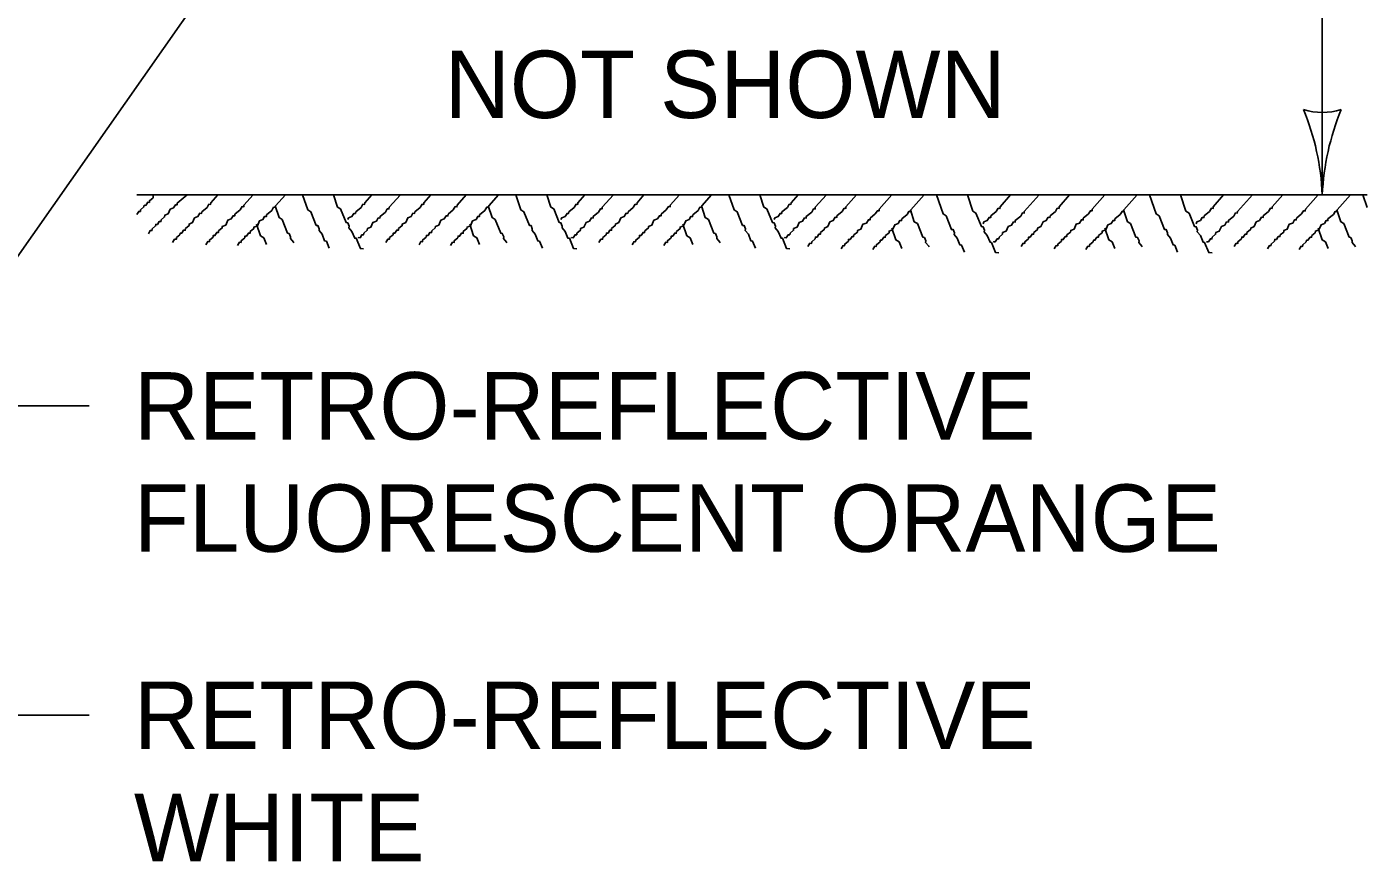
# Model space of a CAD drawing. Extents: x 49991.4 to 50024.6, y 49987.6 to 50011.4.
# Drawn here: x 50012.267 to 50013.46, y 49996.215 to 49996.958 of the extents above; entities that cross this region are included whole.
import ezdxf

# ---------------------------------------------------------------- set-up
doc = ezdxf.new("R2010")
doc.units = 0
for name, color, linetype in [('Level 1', 7, 'Continuous'), ('Level 2', 7, 'Continuous'), ('Level 3', 7, 'Continuous')]:
    doc.layers.add(name, color=color, linetype=linetype)

msp = doc.modelspace()

# ---------------------------------------------------------------- linework, layer by layer
at = {"layer": 'Level 1'}
for points in [[(50012.3796, 49996.8086), (50012.3794, 49996.806), (50012.3762, 49996.8033), (50012.3761, 49996.8018), (50012.3746, 49996.802), (50012.3729, 49996.7992), (50012.3715, 49996.7993), (50012.3713, 49996.7978), (50012.3682, 49996.7952), (50012.3681, 49996.7938), (50012.3666, 49996.7939), (50012.365, 49996.7912)], [(50012.4098, 49996.8086), (50012.4009, 49996.8012), (50012.4008, 49996.7997), (50012.3994, 49996.7998), (50012.3977, 49996.7971), (50012.3947, 49996.7958), (50012.3928, 49996.7917), (50012.3898, 49996.7904), (50012.3897, 49996.789), (50012.3865, 49996.7863), (50012.3864, 49996.7848), (50012.3849, 49996.7849), (50012.3832, 49996.7822), (50012.3818, 49996.7823), (50012.3816, 49996.7809), (50012.3785, 49996.7782), (50012.3784, 49996.7767), (50012.3769, 49996.7769), (50012.3752, 49996.774)], [(50012.4369, 49996.8086), (50012.4307, 49996.8016), (50012.4306, 49996.8001), (50012.4291, 49996.8002), (50012.4274, 49996.7974), (50012.4227, 49996.7934), (50012.4225, 49996.792), (50012.421, 49996.7922), (50012.4193, 49996.7894), (50012.4164, 49996.7881), (50012.4145, 49996.7839), (50012.4115, 49996.7826), (50012.4114, 49996.7812), (50012.4081, 49996.7786), (50012.408, 49996.7771), (50012.4066, 49996.7772), (50012.4049, 49996.7745), (50012.4035, 49996.7746), (50012.4033, 49996.7731), (50012.4002, 49996.7705), (50012.4001, 49996.769), (50012.3986, 49996.7691), (50012.3968, 49996.7663)], [(50012.4684, 49996.8086), (50012.4602, 49996.7994), (50012.4601, 49996.7979), (50012.4586, 49996.7981), (50012.4568, 49996.7953), (50012.4522, 49996.7913), (50012.4521, 49996.7899), (50012.4506, 49996.79), (50012.4489, 49996.7871), (50012.4458, 49996.786), (50012.444, 49996.7817), (50012.441, 49996.7805), (50012.4409, 49996.7791), (50012.4377, 49996.7765), (50012.4375, 49996.775), (50012.4361, 49996.7751), (50012.4344, 49996.7723), (50012.4329, 49996.7725), (50012.4328, 49996.771), (50012.4296, 49996.7683), (50012.4295, 49996.7668), (50012.4281, 49996.767), (50012.4264, 49996.7642)], [(50012.4971, 49996.8086), (50012.4884, 49996.7988), (50012.4882, 49996.7974), (50012.4867, 49996.7975), (50012.4851, 49996.7947), (50012.4803, 49996.7907), (50012.4802, 49996.7893), (50012.4787, 49996.7894), (50012.4771, 49996.7866), (50012.4741, 49996.7854), (50012.4722, 49996.7811), (50012.4691, 49996.7799), (50012.469, 49996.7785), (50012.4658, 49996.7759), (50012.4657, 49996.7744), (50012.4643, 49996.7745), (50012.4625, 49996.7717), (50012.4612, 49996.7718), (50012.461, 49996.7704), (50012.4578, 49996.7677), (50012.4577, 49996.7663), (50012.4563, 49996.7664), (50012.4545, 49996.7636)], [(50012.5125, 49996.8086), (50012.5171, 49996.7952), (50012.5198, 49996.7935), (50012.5246, 49996.7813), (50012.5261, 49996.7812), (50012.5272, 49996.7783), (50012.5271, 49996.7768), (50012.5298, 49996.7737), (50012.5321, 49996.7676), (50012.5336, 49996.7674), (50012.5362, 49996.7611)], [(50012.54, 49996.8086), (50012.5436, 49996.7977), (50012.5463, 49996.796), (50012.5512, 49996.7839), (50012.5527, 49996.7838), (50012.5539, 49996.7807), (50012.5537, 49996.7792), (50012.5564, 49996.7761), (50012.5589, 49996.77), (50012.5602, 49996.7699), (50012.5639, 49996.7608), (50012.5668, 49996.7606)], [(50012.574, 49996.8086), (50012.5678, 49996.8015), (50012.5677, 49996.8), (50012.5662, 49996.8002), (50012.5645, 49996.7974), (50012.5597, 49996.7934), (50012.5595, 49996.792), (50012.5581, 49996.7921), (50012.5564, 49996.7893), (50012.5534, 49996.7881), (50012.5527, 49996.7865)], [(50012.5995, 49996.8086), (50012.5894, 49996.7975), (50012.5893, 49996.796), (50012.5878, 49996.7961), (50012.5862, 49996.7933), (50012.5814, 49996.7894), (50012.5813, 49996.7879), (50012.5798, 49996.7881), (50012.5781, 49996.7853), (50012.5751, 49996.784), (50012.5732, 49996.7798), (50012.5701, 49996.7786), (50012.57, 49996.7771), (50012.5669, 49996.7744), (50012.5667, 49996.773), (50012.5653, 49996.7731), (50012.5636, 49996.7704), (50012.5622, 49996.7705), (50012.5622, 49996.7701)], [(50012.6266, 49996.8086), (50012.6204, 49996.8016), (50012.6203, 49996.8001), (50012.6188, 49996.8002), (50012.6171, 49996.7974), (50012.6124, 49996.7934), (50012.6122, 49996.792), (50012.6107, 49996.7922), (50012.609, 49996.7894), (50012.6061, 49996.7881), (50012.6042, 49996.7839), (50012.6012, 49996.7826), (50012.6011, 49996.7812), (50012.5978, 49996.7786), (50012.5977, 49996.7771), (50012.5963, 49996.7772), (50012.5946, 49996.7745), (50012.5932, 49996.7746), (50012.593, 49996.7731), (50012.5899, 49996.7705), (50012.5898, 49996.769), (50012.5883, 49996.7691), (50012.5865, 49996.7663)], [(50012.6581, 49996.8086), (50012.6499, 49996.7994), (50012.6498, 49996.7979), (50012.6483, 49996.7981), (50012.6465, 49996.7953), (50012.6419, 49996.7913), (50012.6418, 49996.7899), (50012.6403, 49996.79), (50012.6386, 49996.7871), (50012.6355, 49996.786), (50012.6337, 49996.7817), (50012.6307, 49996.7805), (50012.6306, 49996.7791), (50012.6274, 49996.7765), (50012.6272, 49996.775), (50012.6258, 49996.7751), (50012.6241, 49996.7723), (50012.6226, 49996.7725), (50012.6225, 49996.771), (50012.6193, 49996.7683), (50012.6192, 49996.7668), (50012.6178, 49996.767), (50012.6161, 49996.7642)], [(50012.6868, 49996.8086), (50012.6781, 49996.7988), (50012.6779, 49996.7974), (50012.6764, 49996.7975), (50012.6748, 49996.7947), (50012.67, 49996.7907), (50012.6699, 49996.7893), (50012.6684, 49996.7894), (50012.6668, 49996.7866), (50012.6638, 49996.7854), (50012.6619, 49996.7811), (50012.6588, 49996.7799), (50012.6587, 49996.7785), (50012.6555, 49996.7759), (50012.6554, 49996.7744), (50012.654, 49996.7745), (50012.6522, 49996.7717), (50012.6509, 49996.7718), (50012.6507, 49996.7704), (50012.6475, 49996.7677), (50012.6474, 49996.7663), (50012.646, 49996.7664), (50012.6442, 49996.7636)], [(50012.7022, 49996.8086), (50012.7068, 49996.7952), (50012.7095, 49996.7935), (50012.7143, 49996.7813), (50012.7158, 49996.7812), (50012.7169, 49996.7783), (50012.7168, 49996.7768), (50012.7195, 49996.7737), (50012.7218, 49996.7676), (50012.7233, 49996.7674), (50012.7259, 49996.7611)], [(50012.7297, 49996.8086), (50012.7333, 49996.7977), (50012.736, 49996.796), (50012.7409, 49996.7839), (50012.7424, 49996.7838), (50012.7436, 49996.7807), (50012.7434, 49996.7792), (50012.7461, 49996.7761), (50012.7486, 49996.77), (50012.7499, 49996.7699), (50012.7536, 49996.7608), (50012.7565, 49996.7606)], [(50012.7637, 49996.8086), (50012.7575, 49996.8015), (50012.7574, 49996.8), (50012.7559, 49996.8002), (50012.7542, 49996.7974), (50012.7494, 49996.7934), (50012.7492, 49996.792), (50012.7478, 49996.7921), (50012.7461, 49996.7893), (50012.7431, 49996.7881), (50012.7424, 49996.7865)], [(50012.7892, 49996.8086), (50012.7791, 49996.7975), (50012.779, 49996.796), (50012.7775, 49996.7961), (50012.7759, 49996.7933), (50012.7711, 49996.7894), (50012.771, 49996.7879), (50012.7695, 49996.7881), (50012.7678, 49996.7853), (50012.7648, 49996.784), (50012.7629, 49996.7798), (50012.7598, 49996.7786), (50012.7597, 49996.7771), (50012.7566, 49996.7744), (50012.7564, 49996.773), (50012.755, 49996.7731), (50012.7533, 49996.7704), (50012.7519, 49996.7705), (50012.7519, 49996.7701)], [(50012.8163, 49996.8086), (50012.8101, 49996.8016), (50012.81, 49996.8001), (50012.8085, 49996.8002), (50012.8068, 49996.7974), (50012.8021, 49996.7934), (50012.8019, 49996.792), (50012.8004, 49996.7922), (50012.7987, 49996.7894), (50012.7958, 49996.7881), (50012.7939, 49996.7839), (50012.7909, 49996.7826), (50012.7908, 49996.7812), (50012.7875, 49996.7786), (50012.7874, 49996.7771), (50012.786, 49996.7772), (50012.7843, 49996.7745), (50012.7829, 49996.7746), (50012.7827, 49996.7731), (50012.7796, 49996.7705), (50012.7795, 49996.769), (50012.778, 49996.7691), (50012.7762, 49996.7663)], [(50012.8478, 49996.8086), (50012.8396, 49996.7994), (50012.8395, 49996.7979), (50012.838, 49996.7981), (50012.8362, 49996.7953), (50012.8316, 49996.7913), (50012.8315, 49996.7899), (50012.83, 49996.79), (50012.8283, 49996.7871), (50012.8252, 49996.786), (50012.8234, 49996.7817), (50012.8204, 49996.7805), (50012.8203, 49996.7791), (50012.8171, 49996.7765), (50012.8169, 49996.775), (50012.8155, 49996.7751), (50012.8138, 49996.7723), (50012.8123, 49996.7725), (50012.8122, 49996.771), (50012.809, 49996.7683), (50012.8089, 49996.7668), (50012.8075, 49996.767), (50012.8058, 49996.7642)], [(50012.8765, 49996.8086), (50012.8678, 49996.7988), (50012.8676, 49996.7974), (50012.8661, 49996.7975), (50012.8645, 49996.7947), (50012.8597, 49996.7907), (50012.8596, 49996.7893), (50012.8581, 49996.7894), (50012.8565, 49996.7866), (50012.8535, 49996.7854), (50012.8516, 49996.7811), (50012.8485, 49996.7799), (50012.8484, 49996.7785), (50012.8452, 49996.7759), (50012.8451, 49996.7744), (50012.8437, 49996.7745), (50012.8419, 49996.7717), (50012.8406, 49996.7718), (50012.8404, 49996.7704), (50012.8372, 49996.7677), (50012.8371, 49996.7663), (50012.8357, 49996.7664), (50012.8339, 49996.7636)], [(50012.8919, 49996.8086), (50012.8965, 49996.7952), (50012.8992, 49996.7935), (50012.904, 49996.7813), (50012.9055, 49996.7812), (50012.9066, 49996.7783), (50012.9065, 49996.7768), (50012.9092, 49996.7737), (50012.9115, 49996.7676), (50012.913, 49996.7674), (50012.9156, 49996.7611)], [(50012.9194, 49996.8086), (50012.923, 49996.7977), (50012.9257, 49996.796), (50012.9306, 49996.7839), (50012.9321, 49996.7838), (50012.9333, 49996.7807), (50012.9331, 49996.7792), (50012.9358, 49996.7761), (50012.9383, 49996.77), (50012.9396, 49996.7699), (50012.9433, 49996.7608), (50012.9462, 49996.7606)], [(50012.9534, 49996.8086), (50012.9472, 49996.8015), (50012.9471, 49996.8), (50012.9456, 49996.8002), (50012.9439, 49996.7974), (50012.9391, 49996.7934), (50012.9389, 49996.792), (50012.9375, 49996.7921), (50012.9358, 49996.7893), (50012.9328, 49996.7881), (50012.9321, 49996.7865)], [(50012.9789, 49996.8086), (50012.9688, 49996.7975), (50012.9687, 49996.796), (50012.9672, 49996.7961), (50012.9656, 49996.7933), (50012.9608, 49996.7894), (50012.9607, 49996.7879), (50012.9592, 49996.7881), (50012.9575, 49996.7853), (50012.9545, 49996.784), (50012.9526, 49996.7798), (50012.9495, 49996.7786), (50012.9494, 49996.7771), (50012.9463, 49996.7744), (50012.9461, 49996.773), (50012.9447, 49996.7731), (50012.943, 49996.7704), (50012.9416, 49996.7705), (50012.9416, 49996.7701)], [(50013.0054, 49996.8086), (50012.9961, 49996.798), (50012.996, 49996.7965), (50012.9945, 49996.7966), (50012.9928, 49996.7938), (50012.9881, 49996.7898), (50012.9879, 49996.7884), (50012.9864, 49996.7886), (50012.9847, 49996.7858), (50012.9818, 49996.7845), (50012.9799, 49996.7803), (50012.9769, 49996.779), (50012.9768, 49996.7776), (50012.9735, 49996.775), (50012.9734, 49996.7735), (50012.972, 49996.7736), (50012.9703, 49996.7709), (50012.9689, 49996.771), (50012.9687, 49996.7695), (50012.9656, 49996.7669), (50012.9655, 49996.7654), (50012.964, 49996.7655), (50012.9622, 49996.7627)], [(50013.0369, 49996.8086), (50013.0256, 49996.7958), (50013.0255, 49996.7943), (50013.024, 49996.7945), (50013.0222, 49996.7917), (50013.0176, 49996.7877), (50013.0175, 49996.7863), (50013.016, 49996.7864), (50013.0143, 49996.7835), (50013.0112, 49996.7824), (50013.0094, 49996.7781), (50013.0064, 49996.7769), (50013.0063, 49996.7755), (50013.0031, 49996.7729), (50013.0029, 49996.7714), (50013.0015, 49996.7715), (50012.9998, 49996.7687), (50012.9983, 49996.7689), (50012.9982, 49996.7674), (50012.995, 49996.7647), (50012.9949, 49996.7632), (50012.9935, 49996.7634), (50012.9918, 49996.7606)], [(50013.0657, 49996.8086), (50013.0538, 49996.7952), (50013.0536, 49996.7938), (50013.0521, 49996.7939), (50013.0505, 49996.7911), (50013.0457, 49996.7871), (50013.0456, 49996.7857), (50013.0441, 49996.7858), (50013.0425, 49996.783), (50013.0395, 49996.7818), (50013.0376, 49996.7775), (50013.0345, 49996.7763), (50013.0344, 49996.7749), (50013.0312, 49996.7723), (50013.0311, 49996.7708), (50013.0297, 49996.7709), (50013.0279, 49996.7681), (50013.0266, 49996.7682), (50013.0264, 49996.7668), (50013.0232, 49996.7641), (50013.0231, 49996.7627), (50013.0217, 49996.7628), (50013.0199, 49996.76)], [(50013.0766, 49996.8086), (50013.0825, 49996.7916), (50013.0852, 49996.7899), (50013.09, 49996.7777), (50013.0915, 49996.7776), (50013.0926, 49996.7747), (50013.0925, 49996.7732), (50013.0952, 49996.7701), (50013.0975, 49996.764), (50013.099, 49996.7638), (50013.1016, 49996.7575)], [(50013.1042, 49996.8086), (50013.109, 49996.7941), (50013.1117, 49996.7924), (50013.1166, 49996.7803), (50013.1181, 49996.7802), (50013.1193, 49996.7771), (50013.1191, 49996.7756), (50013.1218, 49996.7725), (50013.1243, 49996.7664), (50013.1256, 49996.7663), (50013.1293, 49996.7572), (50013.1322, 49996.757)], [(50013.1425, 49996.8086), (50013.1332, 49996.7979), (50013.1331, 49996.7964), (50013.1316, 49996.7966), (50013.1299, 49996.7938), (50013.1251, 49996.7898), (50013.1249, 49996.7884), (50013.1235, 49996.7885), (50013.1218, 49996.7857), (50013.1188, 49996.7845), (50013.1181, 49996.7829)], [(50013.1681, 49996.8086), (50013.1548, 49996.7939), (50013.1547, 49996.7924), (50013.1532, 49996.7925), (50013.1516, 49996.7897), (50013.1468, 49996.7858), (50013.1467, 49996.7843), (50013.1452, 49996.7845), (50013.1435, 49996.7817), (50013.1405, 49996.7804), (50013.1386, 49996.7762), (50013.1355, 49996.775), (50013.1354, 49996.7735), (50013.1323, 49996.7708), (50013.1321, 49996.7694), (50013.1307, 49996.7695), (50013.129, 49996.7668), (50013.1276, 49996.7669), (50013.1276, 49996.7665)], [(50013.1951, 49996.8086), (50013.1858, 49996.798), (50013.1857, 49996.7965), (50013.1842, 49996.7966), (50013.1825, 49996.7938), (50013.1778, 49996.7898), (50013.1776, 49996.7884), (50013.1761, 49996.7886), (50013.1744, 49996.7858), (50013.1715, 49996.7845), (50013.1696, 49996.7803), (50013.1666, 49996.779), (50013.1665, 49996.7776), (50013.1632, 49996.775), (50013.1631, 49996.7735), (50013.1617, 49996.7736), (50013.16, 49996.7709), (50013.1586, 49996.771), (50013.1584, 49996.7695), (50013.1553, 49996.7669), (50013.1552, 49996.7654), (50013.1537, 49996.7655), (50013.1519, 49996.7627)], [(50013.2266, 49996.8086), (50013.2153, 49996.7958), (50013.2152, 49996.7943), (50013.2137, 49996.7945), (50013.2119, 49996.7917), (50013.2073, 49996.7877), (50013.2072, 49996.7863), (50013.2057, 49996.7864), (50013.204, 49996.7835), (50013.2009, 49996.7824), (50013.1991, 49996.7781), (50013.1961, 49996.7769), (50013.196, 49996.7755), (50013.1928, 49996.7729), (50013.1926, 49996.7714), (50013.1912, 49996.7715), (50013.1895, 49996.7687), (50013.188, 49996.7689), (50013.1879, 49996.7674), (50013.1847, 49996.7647), (50013.1846, 49996.7632), (50013.1832, 49996.7634), (50013.1815, 49996.7606)], [(50013.2554, 49996.8086), (50013.2435, 49996.7952), (50013.2433, 49996.7938), (50013.2418, 49996.7939), (50013.2402, 49996.7911), (50013.2354, 49996.7871), (50013.2353, 49996.7857), (50013.2338, 49996.7858), (50013.2322, 49996.783), (50013.2292, 49996.7818), (50013.2273, 49996.7775), (50013.2242, 49996.7763), (50013.2241, 49996.7749), (50013.2209, 49996.7723), (50013.2208, 49996.7708), (50013.2194, 49996.7709), (50013.2176, 49996.7681), (50013.2163, 49996.7682), (50013.2161, 49996.7668), (50013.2129, 49996.7641), (50013.2128, 49996.7627), (50013.2114, 49996.7628), (50013.2096, 49996.76)], [(50013.2663, 49996.8086), (50013.2722, 49996.7916), (50013.2749, 49996.7899), (50013.2797, 49996.7777), (50013.2812, 49996.7776), (50013.2823, 49996.7747), (50013.2822, 49996.7732), (50013.2849, 49996.7701), (50013.2872, 49996.764), (50013.2887, 49996.7638), (50013.2913, 49996.7575)], [(50013.2939, 49996.8086), (50013.2987, 49996.7941), (50013.3014, 49996.7924), (50013.3063, 49996.7803), (50013.3078, 49996.7802), (50013.309, 49996.7771), (50013.3088, 49996.7756), (50013.3115, 49996.7725), (50013.314, 49996.7664), (50013.3153, 49996.7663), (50013.319, 49996.7572), (50013.3219, 49996.757)], [(50013.3322, 49996.8086), (50013.3229, 49996.7979), (50013.3228, 49996.7964), (50013.3213, 49996.7966), (50013.3196, 49996.7938), (50013.3148, 49996.7898), (50013.3146, 49996.7884), (50013.3132, 49996.7885), (50013.3115, 49996.7857), (50013.3085, 49996.7845), (50013.3078, 49996.7829)], [(50013.3578, 49996.8086), (50013.3445, 49996.7939), (50013.3444, 49996.7924), (50013.3429, 49996.7925), (50013.3413, 49996.7897), (50013.3365, 49996.7858), (50013.3364, 49996.7843), (50013.3349, 49996.7845), (50013.3332, 49996.7817), (50013.3302, 49996.7804), (50013.3283, 49996.7762), (50013.3252, 49996.775), (50013.3251, 49996.7735), (50013.322, 49996.7708), (50013.3218, 49996.7694), (50013.3204, 49996.7695), (50013.3187, 49996.7668), (50013.3173, 49996.7669), (50013.3173, 49996.7665)], [(50013.3849, 49996.8086), (50013.3755, 49996.798), (50013.3754, 49996.7965), (50013.3739, 49996.7966), (50013.3722, 49996.7938), (50013.3675, 49996.7898), (50013.3673, 49996.7884), (50013.3658, 49996.7886), (50013.3641, 49996.7858), (50013.3612, 49996.7845), (50013.3593, 49996.7803), (50013.3563, 49996.779), (50013.3562, 49996.7776), (50013.3529, 49996.775), (50013.3528, 49996.7735), (50013.3514, 49996.7736), (50013.3497, 49996.7709), (50013.3483, 49996.771), (50013.3481, 49996.7695), (50013.345, 49996.7669), (50013.3449, 49996.7654), (50013.3434, 49996.7655), (50013.3416, 49996.7627)], [(50013.4164, 49996.8086), (50013.405, 49996.7958), (50013.4049, 49996.7943), (50013.4034, 49996.7945), (50013.4016, 49996.7917), (50013.397, 49996.7877), (50013.3969, 49996.7863), (50013.3954, 49996.7864), (50013.3937, 49996.7835), (50013.3906, 49996.7824), (50013.3888, 49996.7781), (50013.3858, 49996.7769), (50013.3857, 49996.7755), (50013.3825, 49996.7729), (50013.3823, 49996.7714), (50013.3809, 49996.7715), (50013.3792, 49996.7687), (50013.3777, 49996.7689), (50013.3776, 49996.7674), (50013.3744, 49996.7647), (50013.3743, 49996.7632), (50013.3729, 49996.7634), (50013.3712, 49996.7606)], [(50013.4451, 49996.8086), (50013.4332, 49996.7952), (50013.433, 49996.7938), (50013.4315, 49996.7939), (50013.4299, 49996.7911), (50013.4251, 49996.7871), (50013.425, 49996.7857), (50013.4235, 49996.7858), (50013.4219, 49996.783), (50013.4189, 49996.7818), (50013.417, 49996.7775), (50013.4139, 49996.7763), (50013.4138, 49996.7749), (50013.4106, 49996.7723), (50013.4105, 49996.7708), (50013.4091, 49996.7709), (50013.4073, 49996.7681), (50013.406, 49996.7682), (50013.4058, 49996.7668), (50013.4026, 49996.7641), (50013.4025, 49996.7627), (50013.4011, 49996.7628), (50013.3993, 49996.76)], [(50013.4561, 49996.8086), (50013.46, 49996.7972)], [(50012.488, 49996.7988), (50012.4915, 49996.7883), (50012.4942, 49996.7866), (50012.4991, 49996.7744), (50012.5005, 49996.7743), (50012.5018, 49996.7713), (50012.5016, 49996.7698), (50012.5043, 49996.7666), (50012.5046, 49996.7659)], [(50012.6777, 49996.7988), (50012.6812, 49996.7883), (50012.6839, 49996.7866), (50012.6888, 49996.7744), (50012.6902, 49996.7743), (50012.6915, 49996.7713), (50012.6913, 49996.7698), (50012.694, 49996.7666), (50012.6943, 49996.7659)], [(50012.8674, 49996.7988), (50012.8709, 49996.7883), (50012.8736, 49996.7866), (50012.8785, 49996.7744), (50012.8799, 49996.7743), (50012.8812, 49996.7713), (50012.881, 49996.7698), (50012.8837, 49996.7666), (50012.884, 49996.7659)], [(50013.0534, 49996.7952), (50013.0569, 49996.7847), (50013.0596, 49996.783), (50013.0645, 49996.7708), (50013.0659, 49996.7707), (50013.0672, 49996.7677), (50013.067, 49996.7662), (50013.0697, 49996.763), (50013.07, 49996.7623)], [(50013.2431, 49996.7952), (50013.2466, 49996.7847), (50013.2493, 49996.783), (50013.2542, 49996.7708), (50013.2556, 49996.7707), (50013.2569, 49996.7677), (50013.2567, 49996.7662), (50013.2594, 49996.763), (50013.2597, 49996.7623)], [(50013.4329, 49996.7952), (50013.4364, 49996.7847), (50013.4391, 49996.783), (50013.444, 49996.7708), (50013.4454, 49996.7707), (50013.4467, 49996.7677), (50013.4465, 49996.7662), (50013.4492, 49996.763), (50013.4495, 49996.7623)], [(50012.4715, 49996.7826), (50012.475, 49996.7721), (50012.4779, 49996.7704), (50012.4803, 49996.7644)], [(50012.6612, 49996.7826), (50012.6647, 49996.7721), (50012.6676, 49996.7704), (50012.67, 49996.7644)], [(50012.8509, 49996.7826), (50012.8544, 49996.7721), (50012.8573, 49996.7704), (50012.8597, 49996.7644)], [(50013.0369, 49996.779), (50013.0404, 49996.7685), (50013.0433, 49996.7668), (50013.0457, 49996.7608)], [(50013.2266, 49996.779), (50013.2301, 49996.7685), (50013.233, 49996.7668), (50013.2354, 49996.7608)], [(50013.4164, 49996.779), (50013.4199, 49996.7685), (50013.4228, 49996.7668), (50013.4252, 49996.7608)]]:
    msp.add_lwpolyline(points, dxfattribs=at)
at = {"layer": 'Level 3'}
for p, q in [((50013.42, 49998.0086), (50013.42, 49996.8086)), ((50012.5073, 49997.1086), (50012.1656, 49996.6207)), ((50013.46, 49996.8086), (50012.365, 49996.8086)), ((50012.1656, 49996.6207), (50012.3224, 49996.6207)), ((50011.8076, 49996.3452), (50012.3224, 49996.3452))]:
    msp.add_line(p, q, dxfattribs=at)
for centre, radius, start, end in [((50013.1979, 49996.7994), 0.2223, 2.3605, 22.544), ((50013.42, 49996.9368), 0.0548, 252.1388, 287.8612), ((50013.6527, 49996.7971), 0.233, 157.9228, 177.1727)]:
    msp.add_arc(centre, radius, start, end, dxfattribs=at)

# ---------------------------------------------------------------- texts
at = {"layer": 'Level 2'}
for s, p in [('NOT SHOWN', (50012.639, 49996.877)), ('RETRO-REFLECTIVE', (50012.3624, 49996.5907)), ('FLUORESCENT ORANGE', (50012.3624, 49996.4907)), ('RETRO-REFLECTIVE', (50012.3624, 49996.3152)), ('WHITE', (50012.3624, 49996.2152))]:
    msp.add_text(s, height=0.06, dxfattribs=at).set_placement(p)

doc.saveas('drawing.dxf')
